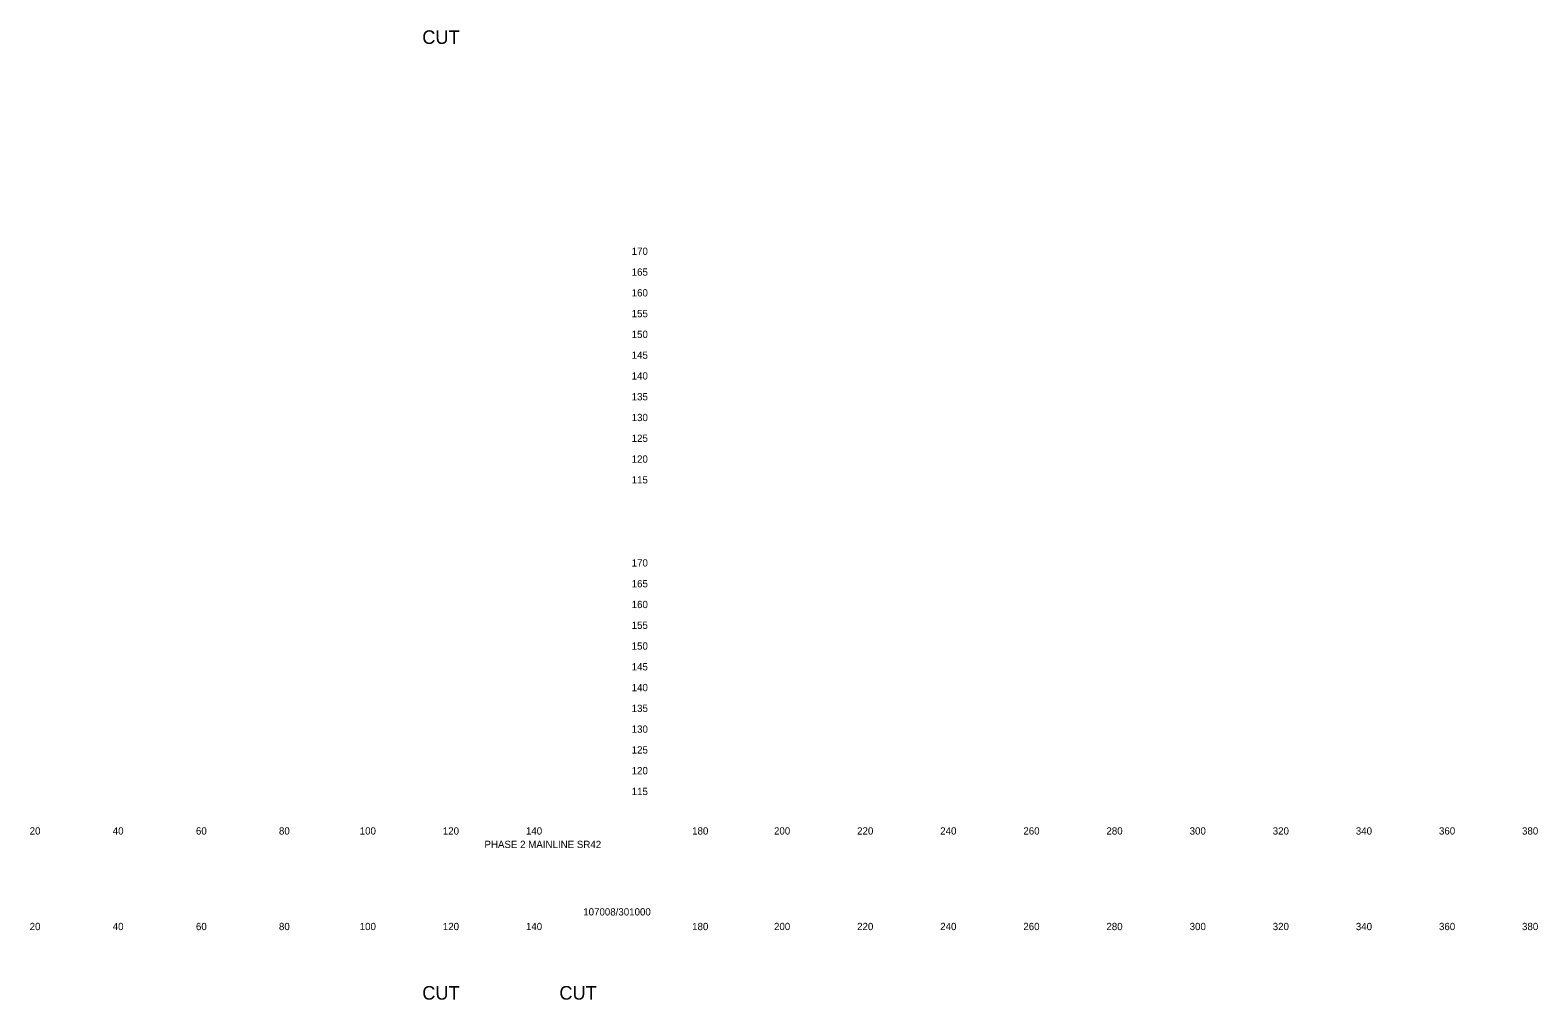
# Model space of a CAD drawing. Extents: x 21281 to 22024, y 6472 to 15208.
# Drawn here: x 21661.4 to 22024.2, y 13335.6 to 13568.9 of the extents above; entities that cross this region are included whole.
import ezdxf

# ---------------------------------------------------------------- set-up
doc = ezdxf.new("R2010")
doc.units = 0
doc.layers.add('XS_SHEET_LABELS_ELEVATION', color=7, linetype='Continuous')
doc.layers.add('XS_SHEET_LABELS_OFFSET', color=7, linetype='Continuous')

msp = doc.modelspace()

# ---------------------------------------------------------------- texts
at = {"layer": 'XS_SHEET_LABELS_ELEVATION'}
for s, p in [('  170  ', (21804.84, 13514.84)), ('  165  ', (21804.84, 13509.84)), ('  160  ', (21804.84, 13504.84)), ('  155  ', (21804.84, 13499.84)), ('  150  ', (21804.84, 13494.84)), ('  145  ', (21804.84, 13489.84)), ('  140  ', (21804.84, 13484.84)), ('  135  ', (21804.84, 13479.84)), ('  130  ', (21804.84, 13474.84)), ('  125  ', (21804.84, 13469.84)), ('  120  ', (21804.84, 13464.84)), ('  115  ', (21804.84, 13459.84)), ('  170  ', (21804.84, 13439.84)), ('  165  ', (21804.84, 13434.84)), ('  160  ', (21804.84, 13429.84)), ('  155  ', (21804.84, 13424.84)), ('  150  ', (21804.84, 13419.84)), ('  145  ', (21804.84, 13414.84)), ('  140  ', (21804.84, 13409.84)), ('  135  ', (21804.84, 13404.84)), ('  130  ', (21804.84, 13399.84)), ('  125  ', (21804.84, 13394.84)), ('  120  ', (21804.84, 13389.84)), ('  115  ', (21804.84, 13384.84))]:
    msp.add_text(s, height=1.75, dxfattribs=at).set_placement(p)
at = {"layer": 'XS_SHEET_LABELS_OFFSET'}
for s, height, p in [('CUT', 3.273, (21755.74, 13565.61)), ('  20  ', 1.75, (21659.95, 13375.34)), ('  40  ', 1.75, (21679.95, 13375.34)), ('  60  ', 1.75, (21699.97, 13375.34)), ('  80  ', 1.75, (21719.95, 13375.34)), ('  100  ', 1.75, (21739.39, 13375.34)), ('  120  ', 1.75, (21759.39, 13375.34)), ('  140  ', 1.75, (21779.39, 13375.34)), ('  180  ', 1.75, (21819.39, 13375.34)), ('  200  ', 1.75, (21839.1, 13375.34)), ('  220  ', 1.75, (21859.1, 13375.34)), ('  240  ', 1.75, (21879.1, 13375.34)), ('  260  ', 1.75, (21899.11, 13375.34)), ('  280  ', 1.75, (21919.1, 13375.34)), ('  300  ', 1.75, (21939.13, 13375.34)), ('  320  ', 1.75, (21959.13, 13375.34)), ('  340  ', 1.75, (21979.13, 13375.34)), ('  360  ', 1.75, (21999.14, 13375.34)), ('  380  ', 1.75, (22019.13, 13375.34)), ('PHASE 2 MAINLINE SR42', 1.75, (21770.71, 13372.1)), ('107008/301000', 1.75, (21794.48, 13355.86)), ('  20  ', 1.75, (21659.95, 13352.34)), ('  40  ', 1.75, (21679.95, 13352.34)), ('  60  ', 1.75, (21699.97, 13352.34)), ('  80  ', 1.75, (21719.95, 13352.34)), ('  100  ', 1.75, (21739.39, 13352.34)), ('  120  ', 1.75, (21759.39, 13352.34)), ('  140  ', 1.75, (21779.39, 13352.34)), ('  180  ', 1.75, (21819.39, 13352.34)), ('  200  ', 1.75, (21839.1, 13352.34)), ('  220  ', 1.75, (21859.1, 13352.34)), ('  240  ', 1.75, (21879.1, 13352.34)), ('  260  ', 1.75, (21899.11, 13352.34)), ('  280  ', 1.75, (21919.1, 13352.34)), ('  300  ', 1.75, (21939.13, 13352.34)), ('  320  ', 1.75, (21959.13, 13352.34)), ('  340  ', 1.75, (21979.13, 13352.34)), ('  360  ', 1.75, (21999.14, 13352.34)), ('  380  ', 1.75, (22019.13, 13352.34)), ('CUT', 3.273, (21755.74, 13335.61)), ('CUT', 3.273, (21788.74, 13335.61))]:
    msp.add_text(s, height=height, dxfattribs=at).set_placement(p)

doc.saveas('drawing.dxf')
